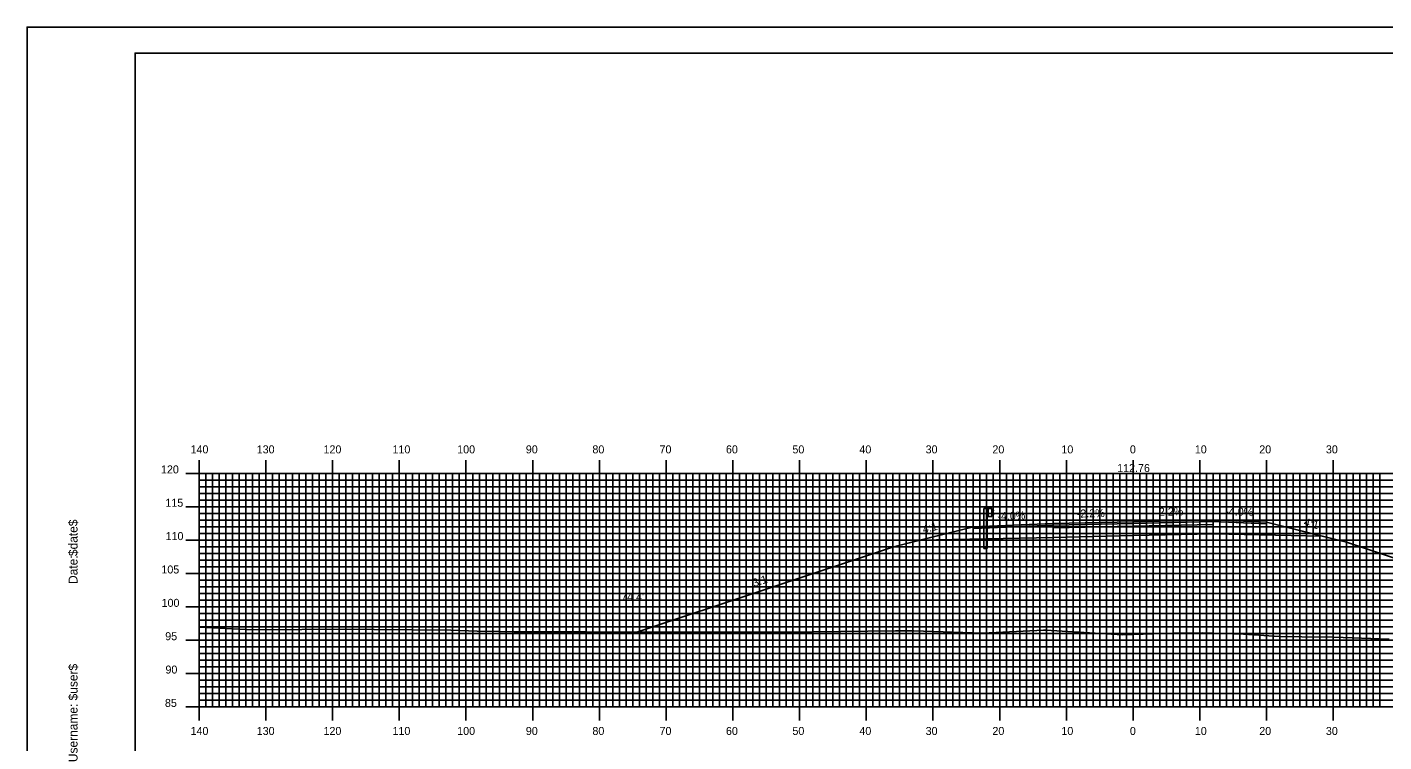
# Model space of a CAD drawing. Extents: x 1786976 to 1787319, y 442591 to 442811.
# Drawn here: x 1786975.8 to 1787179.2, y 442703.4 to 442810.5 of the extents above; entities that cross this region are included whole.
import ezdxf

# ---------------------------------------------------------------- set-up
doc = ezdxf.new("R2010")
doc.units = 0
for name, color, linetype in [('ANNOTATION', 7, 'Continuous'), ('BORDER', 7, 'Continuous'), ('D_Guardrail_Beam_Lt', 7, 'Continuous'), ('D_Roadway_Centerline', 7, 'Continuous'), ('D_Roadway_Centerline_Text', 7, 'Continuous'), ('D_Roadway_Edge_Shoulder', 7, 'Continuous'), ('D_Roadway_Edge_TW', 7, 'Continuous'), ('D_Roadway_Pavement', 7, 'Continuous'), ('D_Roadway_SlopeLines', 7, 'Continuous'), ('D_Roadway_SubGrade', 7, 'Continuous'), ('D_Text_Standard', 7, 'Continuous'), ('H_V ANNOTATION', 7, 'Continuous'), ('MAJOR', 7, 'Continuous'), ('MINOR', 7, 'Continuous'), ('PLOT BOUNDARY', 7, 'Continuous'), ('S_Roadway_Centerline', 7, 'Continuous')]:
    doc.layers.add(name, color=color, linetype=linetype)

msp = doc.modelspace()

# ---------------------------------------------------------------- linework, layer by layer
at = {"layer": 'BORDER'}
msp.add_lwpolyline([(1786991.99, 442596.67), (1787311.99, 442596.67), (1787311.99, 442806.67), (1786991.99, 442806.67)], close=True, dxfattribs=at)
at = {"layer": 'D_Guardrail_Beam_Lt'}
for p, q in [((1787119.23, 442738.39), (1787119.23, 442732.39)), ((1787119.7, 442738.39), (1787119.23, 442738.39)), ((1787120.39, 442738.39), (1787119.7, 442738.39)), ((1787119.7, 442738.39), (1787119.7, 442737.22)), ((1787119.7, 442737.22), (1787120.39, 442737.22)), ((1787119.72, 442732.39), (1787119.72, 442737.22)), ((1787119.76, 442738.39), (1787119.76, 442737.22)), ((1787119.87, 442738.39), (1787119.87, 442737.22)), ((1787120.39, 442737.22), (1787120.39, 442738.39)), ((1787120.39, 442738.3), (1787120.46, 442738.29)), ((1787120.39, 442737.84), (1787120.39, 442737.77)), ((1787120.46, 442737.32), (1787120.39, 442737.3)), ((1787120.62, 442738.04), (1787120.42, 442737.9)), ((1787120.42, 442737.7), (1787120.62, 442737.57)), ((1787120.48, 442738.28), (1787120.62, 442738.18)), ((1787120.62, 442737.42), (1787120.48, 442737.32)), ((1787119.72, 442732.39), (1787119.23, 442732.39))]:
    msp.add_line(p, q, dxfattribs=at)
for centre, major_axis, start_param, end_param in [((1787120.47, 442737.84), (-0.0789, 0), 5.323254, 6.283185), ((1787120.47, 442737.77), (-0.0789, 0), 6.283185, 7.243116), ((1787120.45, 442738.25), (0.0417, 0), 0.959931, 1.376053), ((1787120.45, 442737.36), (0.0417, 0), 4.907132, 5.323254), ((1787120.57, 442738.11), (0.0877, 0), 5.323254, 7.243116), ((1787120.57, 442737.49), (0.0877, 0), 5.323254, 7.243116)]:
    msp.add_ellipse(centre, major_axis=major_axis, ratio=0.995501, start_param=start_param, end_param=end_param, dxfattribs=at)
at = {"layer": 'D_Roadway_Centerline'}
msp.add_lwpolyline([(1787067.21, 442719.86), (1787105.66, 442732.68), (1787109.64, 442733.68), (1787117.66, 442735.68), (1787129.59, 442736.16), (1787141.59, 442736.42), (1787153.59, 442736.69), (1787161.59, 442736.37), (1787169.95, 442734.28), (1787173.59, 442733.37), (1787217.6, 442718.7)], dxfattribs=at)
at = {"layer": 'D_Roadway_Edge_Shoulder'}
for points in [[(1787153.59, 442736.69), (1787161.59, 442736.37), (1787161.59, 442736.12), (1787153.59, 442736.44)], [(1787129.59, 442736.16), (1787117.66, 442735.68), (1787117.66, 442735.43), (1787129.59, 442735.91)]]:
    msp.add_lwpolyline(points, close=True, dxfattribs=at)
at = {"layer": 'D_Roadway_Edge_TW'}
msp.add_lwpolyline([(1787129.59, 442735.91), (1787129.59, 442736.16), (1787141.59, 442736.42), (1787153.59, 442736.69), (1787153.59, 442736.44), (1787141.59, 442736.17)], close=True, dxfattribs=at)
at = {"layer": 'D_Roadway_Pavement'}
msp.add_lwpolyline([(1787129.59, 442735.49), (1787129.59, 442735.91), (1787141.59, 442736.17), (1787153.59, 442736.44), (1787153.59, 442736.02), (1787141.59, 442735.76)], close=True, dxfattribs=at)
at = {"layer": 'D_Roadway_SlopeLines'}
for points in [[(1787117.66, 442735.68), (1787105.66, 442732.68), (1787067.21, 442719.86)], [(1787161.59, 442736.37), (1787173.59, 442733.37), (1787217.6, 442718.7)]]:
    msp.add_lwpolyline(points, dxfattribs=at)
at = {"layer": 'D_Roadway_SubGrade'}
msp.add_lwpolyline([(1787129.59, 442734.08), (1787109.64, 442733.68), (1787117.66, 442735.68), (1787117.66, 442735.43), (1787129.59, 442735.91), (1787141.59, 442736.17), (1787153.59, 442736.44), (1787161.59, 442736.12), (1787161.59, 442736.37), (1787169.95, 442734.28), (1787153.59, 442734.6), (1787141.59, 442734.34)], close=True, dxfattribs=at)
at = {"layer": 'MAJOR'}
for p, q in [((1787001.59, 442745.67), (1787001.59, 442743.67)), ((1787011.59, 442745.67), (1787011.59, 442743.67)), ((1787021.59, 442745.67), (1787021.59, 442743.67)), ((1787031.59, 442745.67), (1787031.59, 442743.67)), ((1787041.59, 442745.67), (1787041.59, 442743.67)), ((1787051.59, 442745.67), (1787051.59, 442743.67)), ((1787061.59, 442745.67), (1787061.59, 442743.67)), ((1787071.59, 442745.67), (1787071.59, 442743.67)), ((1787081.59, 442745.67), (1787081.59, 442743.67)), ((1787091.59, 442745.67), (1787091.59, 442743.67)), ((1787101.59, 442745.67), (1787101.59, 442743.67)), ((1787111.59, 442745.67), (1787111.59, 442743.67)), ((1787121.59, 442745.67), (1787121.59, 442743.67)), ((1787131.59, 442745.67), (1787131.59, 442743.67)), ((1787141.59, 442745.67), (1787141.59, 442743.67)), ((1787151.59, 442745.67), (1787151.59, 442743.67)), ((1787161.59, 442745.67), (1787161.59, 442743.67)), ((1787171.59, 442745.67), (1787171.59, 442743.67)), ((1786999.59, 442743.67), (1787001.59, 442743.67)), ((1787001.59, 442743.67), (1787281.59, 442743.67)), ((1787001.59, 442708.67), (1787001.59, 442743.67)), ((1787001.59, 442708.67), (1787001.59, 442743.67)), ((1787001.59, 442743.67), (1787281.59, 442743.67)), ((1787011.59, 442708.67), (1787011.59, 442743.67)), ((1787021.59, 442708.67), (1787021.59, 442743.67)), ((1787031.59, 442708.67), (1787031.59, 442743.67)), ((1787041.59, 442708.67), (1787041.59, 442743.67)), ((1787051.59, 442708.67), (1787051.59, 442743.67)), ((1787061.59, 442708.67), (1787061.59, 442743.67)), ((1787071.59, 442708.67), (1787071.59, 442743.67)), ((1787081.59, 442708.67), (1787081.59, 442743.67)), ((1787091.59, 442708.67), (1787091.59, 442743.67)), ((1787101.59, 442708.67), (1787101.59, 442743.67)), ((1787111.59, 442708.67), (1787111.59, 442743.67)), ((1787121.59, 442708.67), (1787121.59, 442743.67)), ((1787131.59, 442708.67), (1787131.59, 442743.67)), ((1787141.59, 442708.67), (1787141.59, 442743.67)), ((1787151.59, 442708.67), (1787151.59, 442743.67)), ((1787161.59, 442708.67), (1787161.59, 442743.67)), ((1787171.59, 442708.67), (1787171.59, 442743.67)), ((1786999.59, 442738.67), (1787001.59, 442738.67)), ((1787001.59, 442738.67), (1787281.59, 442738.67)), ((1786999.59, 442733.67), (1787001.59, 442733.67)), ((1787001.59, 442733.67), (1787281.59, 442733.67)), ((1786999.59, 442728.67), (1787001.59, 442728.67)), ((1787001.59, 442728.67), (1787281.59, 442728.67)), ((1786999.59, 442723.67), (1787001.59, 442723.67)), ((1787001.59, 442723.67), (1787281.59, 442723.67)), ((1786999.59, 442718.67), (1787001.59, 442718.67)), ((1787001.59, 442718.67), (1787281.59, 442718.67)), ((1786999.59, 442713.67), (1787001.59, 442713.67)), ((1787001.59, 442713.67), (1787281.59, 442713.67)), ((1786999.59, 442708.67), (1787001.59, 442708.67)), ((1787001.59, 442708.67), (1787281.59, 442708.67)), ((1787001.59, 442708.67), (1787281.59, 442708.67)), ((1787001.59, 442706.66), (1787001.59, 442708.67)), ((1787011.59, 442706.66), (1787011.59, 442708.67)), ((1787021.59, 442706.66), (1787021.59, 442708.67)), ((1787031.59, 442706.66), (1787031.59, 442708.67)), ((1787041.59, 442706.66), (1787041.59, 442708.67)), ((1787051.59, 442706.66), (1787051.59, 442708.67)), ((1787061.59, 442706.66), (1787061.59, 442708.67)), ((1787071.59, 442706.66), (1787071.59, 442708.67)), ((1787081.59, 442706.66), (1787081.59, 442708.67)), ((1787091.59, 442706.66), (1787091.59, 442708.67)), ((1787101.59, 442706.66), (1787101.59, 442708.67)), ((1787111.59, 442706.66), (1787111.59, 442708.67)), ((1787121.59, 442706.66), (1787121.59, 442708.67)), ((1787131.59, 442706.66), (1787131.59, 442708.67)), ((1787141.59, 442706.66), (1787141.59, 442708.67)), ((1787151.59, 442706.66), (1787151.59, 442708.67)), ((1787161.59, 442706.66), (1787161.59, 442708.67)), ((1787171.59, 442706.66), (1787171.59, 442708.67))]:
    msp.add_line(p, q, dxfattribs=at)
at = {"layer": 'MINOR'}
for p, q in [((1787001.59, 442742.67), (1787281.59, 442742.67)), ((1787001.59, 442742.67), (1787003.6, 442742.67)), ((1787002.59, 442708.67), (1787002.59, 442743.67)), ((1787003.59, 442708.67), (1787003.59, 442743.67)), ((1787004.59, 442708.67), (1787004.59, 442743.67)), ((1787005.59, 442708.67), (1787005.59, 442743.67)), ((1787006.59, 442708.67), (1787006.59, 442743.67)), ((1787007.59, 442708.67), (1787007.59, 442743.67)), ((1787008.59, 442708.67), (1787008.59, 442743.67)), ((1787009.59, 442708.67), (1787009.59, 442743.67)), ((1787010.59, 442708.67), (1787010.59, 442743.67)), ((1787012.59, 442708.67), (1787012.59, 442743.67)), ((1787013.59, 442708.67), (1787013.59, 442743.67)), ((1787014.59, 442708.67), (1787014.59, 442743.67)), ((1787015.59, 442708.67), (1787015.59, 442743.67)), ((1787016.59, 442708.67), (1787016.59, 442743.67)), ((1787017.59, 442708.67), (1787017.59, 442743.67)), ((1787018.59, 442708.67), (1787018.59, 442743.67)), ((1787019.59, 442708.67), (1787019.59, 442743.67)), ((1787020.59, 442708.67), (1787020.59, 442743.67)), ((1787022.59, 442708.67), (1787022.59, 442743.67)), ((1787023.59, 442708.67), (1787023.59, 442743.67)), ((1787024.59, 442708.67), (1787024.59, 442743.67)), ((1787025.59, 442708.67), (1787025.59, 442743.67)), ((1787026.59, 442708.67), (1787026.59, 442743.67)), ((1787027.59, 442708.67), (1787027.59, 442743.67)), ((1787028.59, 442708.67), (1787028.59, 442743.67)), ((1787029.59, 442708.67), (1787029.59, 442743.67)), ((1787030.59, 442708.67), (1787030.59, 442743.67)), ((1787032.59, 442708.67), (1787032.59, 442743.67)), ((1787033.59, 442708.67), (1787033.59, 442743.67)), ((1787034.59, 442708.67), (1787034.59, 442743.67)), ((1787035.59, 442708.67), (1787035.59, 442743.67)), ((1787036.59, 442708.67), (1787036.59, 442743.67)), ((1787037.59, 442708.67), (1787037.59, 442743.67)), ((1787038.59, 442708.67), (1787038.59, 442743.67)), ((1787039.59, 442708.67), (1787039.59, 442743.67)), ((1787040.59, 442708.67), (1787040.59, 442743.67)), ((1787042.59, 442708.67), (1787042.59, 442743.67)), ((1787043.59, 442708.67), (1787043.59, 442743.67)), ((1787044.59, 442708.67), (1787044.59, 442743.67)), ((1787045.59, 442708.67), (1787045.59, 442743.67)), ((1787046.59, 442708.67), (1787046.59, 442743.67)), ((1787047.59, 442708.67), (1787047.59, 442743.67)), ((1787048.59, 442708.67), (1787048.59, 442743.67)), ((1787049.59, 442708.67), (1787049.59, 442743.67)), ((1787050.59, 442708.67), (1787050.59, 442743.67)), ((1787052.59, 442708.67), (1787052.59, 442743.67)), ((1787053.59, 442708.67), (1787053.59, 442743.67)), ((1787054.59, 442708.67), (1787054.59, 442743.67)), ((1787055.59, 442708.67), (1787055.59, 442743.67)), ((1787056.59, 442708.67), (1787056.59, 442743.67)), ((1787057.59, 442708.67), (1787057.59, 442743.67)), ((1787058.59, 442708.67), (1787058.59, 442743.67)), ((1787059.59, 442708.67), (1787059.59, 442743.67)), ((1787060.59, 442708.67), (1787060.59, 442743.67)), ((1787062.59, 442708.67), (1787062.59, 442743.67)), ((1787063.59, 442708.67), (1787063.59, 442743.67)), ((1787064.59, 442708.67), (1787064.59, 442743.67)), ((1787065.59, 442708.67), (1787065.59, 442743.67)), ((1787066.59, 442708.67), (1787066.59, 442743.67)), ((1787067.59, 442708.67), (1787067.59, 442743.67)), ((1787068.59, 442708.67), (1787068.59, 442743.67)), ((1787069.59, 442708.67), (1787069.59, 442743.67)), ((1787070.59, 442708.67), (1787070.59, 442743.67)), ((1787072.59, 442708.67), (1787072.59, 442743.67)), ((1787073.59, 442708.67), (1787073.59, 442743.67)), ((1787074.59, 442708.67), (1787074.59, 442743.67)), ((1787075.59, 442708.67), (1787075.59, 442743.67)), ((1787076.59, 442708.67), (1787076.59, 442743.67)), ((1787077.59, 442708.67), (1787077.59, 442743.67)), ((1787078.59, 442708.67), (1787078.59, 442743.67)), ((1787079.59, 442708.67), (1787079.59, 442743.67)), ((1787080.59, 442708.67), (1787080.59, 442743.67)), ((1787082.59, 442708.67), (1787082.59, 442743.67)), ((1787083.59, 442708.67), (1787083.59, 442743.67)), ((1787084.59, 442708.67), (1787084.59, 442743.67)), ((1787085.59, 442708.67), (1787085.59, 442743.67)), ((1787086.59, 442708.67), (1787086.59, 442743.67)), ((1787087.59, 442708.67), (1787087.59, 442743.67)), ((1787088.59, 442708.67), (1787088.59, 442743.67)), ((1787089.59, 442708.67), (1787089.59, 442743.67)), ((1787090.59, 442708.67), (1787090.59, 442743.67)), ((1787092.59, 442708.67), (1787092.59, 442743.67)), ((1787093.59, 442708.67), (1787093.59, 442743.67)), ((1787094.59, 442708.67), (1787094.59, 442743.67)), ((1787095.59, 442708.67), (1787095.59, 442743.67)), ((1787096.59, 442708.67), (1787096.59, 442743.67)), ((1787097.59, 442708.67), (1787097.59, 442743.67)), ((1787098.59, 442708.67), (1787098.59, 442743.67)), ((1787099.59, 442708.67), (1787099.59, 442743.67)), ((1787100.59, 442708.67), (1787100.59, 442743.67)), ((1787102.59, 442708.67), (1787102.59, 442743.67)), ((1787103.59, 442708.67), (1787103.59, 442743.67)), ((1787104.59, 442708.67), (1787104.59, 442743.67)), ((1787105.59, 442708.67), (1787105.59, 442743.67)), ((1787106.59, 442708.67), (1787106.59, 442743.67)), ((1787107.59, 442708.67), (1787107.59, 442743.67)), ((1787108.59, 442708.67), (1787108.59, 442743.67)), ((1787109.59, 442708.67), (1787109.59, 442743.67)), ((1787110.59, 442708.67), (1787110.59, 442743.67)), ((1787112.59, 442708.67), (1787112.59, 442743.67)), ((1787113.59, 442708.67), (1787113.59, 442743.67)), ((1787114.59, 442708.67), (1787114.59, 442743.67)), ((1787115.59, 442708.67), (1787115.59, 442743.67)), ((1787116.59, 442708.67), (1787116.59, 442743.67)), ((1787117.59, 442708.67), (1787117.59, 442743.67)), ((1787118.59, 442708.67), (1787118.59, 442743.67)), ((1787119.59, 442708.67), (1787119.59, 442743.67)), ((1787120.59, 442708.67), (1787120.59, 442743.67)), ((1787122.59, 442708.67), (1787122.59, 442743.67)), ((1787123.59, 442708.67), (1787123.59, 442743.67)), ((1787124.59, 442708.67), (1787124.59, 442743.67)), ((1787125.59, 442708.67), (1787125.59, 442743.67)), ((1787126.59, 442708.67), (1787126.59, 442743.67)), ((1787127.59, 442708.67), (1787127.59, 442743.67)), ((1787128.59, 442708.67), (1787128.59, 442743.67)), ((1787129.59, 442708.67), (1787129.59, 442743.67)), ((1787130.59, 442708.67), (1787130.59, 442743.67)), ((1787132.59, 442708.67), (1787132.59, 442743.67)), ((1787133.59, 442708.67), (1787133.59, 442743.67)), ((1787134.59, 442708.67), (1787134.59, 442743.67)), ((1787135.59, 442708.67), (1787135.59, 442743.67)), ((1787136.59, 442708.67), (1787136.59, 442743.67)), ((1787137.59, 442708.67), (1787137.59, 442743.67)), ((1787138.59, 442708.67), (1787138.59, 442743.67)), ((1787139.59, 442708.67), (1787139.59, 442743.67)), ((1787140.59, 442708.67), (1787140.59, 442743.67)), ((1787142.59, 442708.67), (1787142.59, 442743.67)), ((1787143.59, 442708.67), (1787143.59, 442743.67)), ((1787144.59, 442708.67), (1787144.59, 442743.67)), ((1787145.59, 442708.67), (1787145.59, 442743.67)), ((1787146.59, 442708.67), (1787146.59, 442743.67)), ((1787147.59, 442708.67), (1787147.59, 442743.67)), ((1787148.59, 442708.67), (1787148.59, 442743.67)), ((1787149.59, 442708.67), (1787149.59, 442743.67)), ((1787150.59, 442708.67), (1787150.59, 442743.67)), ((1787152.59, 442708.67), (1787152.59, 442743.67)), ((1787153.59, 442708.67), (1787153.59, 442743.67)), ((1787154.59, 442708.67), (1787154.59, 442743.67)), ((1787155.59, 442708.67), (1787155.59, 442743.67)), ((1787156.59, 442708.67), (1787156.59, 442743.67)), ((1787157.59, 442708.67), (1787157.59, 442743.67)), ((1787158.59, 442708.67), (1787158.59, 442743.67)), ((1787159.59, 442708.67), (1787159.59, 442743.67)), ((1787160.59, 442708.67), (1787160.59, 442743.67)), ((1787162.59, 442708.67), (1787162.59, 442743.67)), ((1787163.59, 442708.67), (1787163.59, 442743.67)), ((1787164.59, 442708.67), (1787164.59, 442743.67)), ((1787165.59, 442708.67), (1787165.59, 442743.67)), ((1787166.59, 442708.67), (1787166.59, 442743.67)), ((1787167.59, 442708.67), (1787167.59, 442743.67)), ((1787168.59, 442708.67), (1787168.59, 442743.67)), ((1787169.59, 442708.67), (1787169.59, 442743.67)), ((1787170.59, 442708.67), (1787170.59, 442743.67)), ((1787172.59, 442708.67), (1787172.59, 442743.67)), ((1787173.59, 442708.67), (1787173.59, 442743.67)), ((1787174.59, 442708.67), (1787174.59, 442743.67)), ((1787175.59, 442708.67), (1787175.59, 442743.67)), ((1787176.59, 442708.67), (1787176.59, 442743.67)), ((1787177.59, 442708.67), (1787177.59, 442743.67)), ((1787178.59, 442708.67), (1787178.59, 442743.67)), ((1787001.59, 442741.67), (1787281.59, 442741.67)), ((1787001.59, 442741.67), (1787003.6, 442741.67)), ((1787001.59, 442740.67), (1787281.59, 442740.67)), ((1787001.59, 442740.67), (1787003.6, 442740.67)), ((1787001.59, 442739.67), (1787281.59, 442739.67)), ((1787001.59, 442739.67), (1787003.6, 442739.67)), ((1787001.59, 442737.67), (1787281.59, 442737.67)), ((1787001.59, 442737.67), (1787003.6, 442737.67)), ((1787001.59, 442736.67), (1787281.59, 442736.67)), ((1787001.59, 442736.67), (1787003.6, 442736.67)), ((1787001.59, 442735.67), (1787281.59, 442735.67)), ((1787001.59, 442735.67), (1787003.6, 442735.67)), ((1787001.59, 442734.67), (1787281.59, 442734.67)), ((1787001.59, 442734.67), (1787003.6, 442734.67)), ((1787001.59, 442732.67), (1787281.59, 442732.67)), ((1787001.59, 442732.67), (1787003.6, 442732.67)), ((1787001.59, 442731.67), (1787281.59, 442731.67)), ((1787001.59, 442731.67), (1787003.6, 442731.67)), ((1787001.59, 442730.67), (1787281.59, 442730.67)), ((1787001.59, 442730.67), (1787003.6, 442730.67)), ((1787001.59, 442729.67), (1787281.59, 442729.67)), ((1787001.59, 442729.67), (1787003.6, 442729.67)), ((1787001.59, 442727.67), (1787281.59, 442727.67)), ((1787001.59, 442727.67), (1787003.6, 442727.67)), ((1787001.59, 442726.67), (1787281.59, 442726.67)), ((1787001.59, 442726.67), (1787003.6, 442726.67)), ((1787001.59, 442725.67), (1787281.59, 442725.67)), ((1787001.59, 442725.67), (1787003.6, 442725.67)), ((1787001.59, 442724.67), (1787281.59, 442724.67)), ((1787001.59, 442724.67), (1787003.6, 442724.67)), ((1787001.59, 442722.67), (1787281.59, 442722.67)), ((1787001.59, 442722.67), (1787003.6, 442722.67)), ((1787001.59, 442721.67), (1787281.59, 442721.67)), ((1787001.59, 442721.67), (1787003.6, 442721.67)), ((1787001.59, 442720.67), (1787281.59, 442720.67)), ((1787001.59, 442720.67), (1787003.6, 442720.67)), ((1787001.59, 442719.67), (1787281.59, 442719.67)), ((1787001.59, 442719.67), (1787003.6, 442719.67)), ((1787001.59, 442717.67), (1787281.59, 442717.67)), ((1787001.59, 442717.67), (1787003.6, 442717.67)), ((1787001.59, 442716.67), (1787281.59, 442716.67)), ((1787001.59, 442716.67), (1787003.6, 442716.67)), ((1787001.59, 442715.67), (1787281.59, 442715.67)), ((1787001.59, 442715.67), (1787003.6, 442715.67)), ((1787001.59, 442714.67), (1787281.59, 442714.67)), ((1787001.59, 442714.67), (1787003.6, 442714.67)), ((1787001.59, 442712.67), (1787281.59, 442712.67)), ((1787001.59, 442712.67), (1787003.6, 442712.67)), ((1787001.59, 442711.67), (1787281.59, 442711.67)), ((1787001.59, 442711.67), (1787003.6, 442711.67)), ((1787001.59, 442710.67), (1787281.59, 442710.67)), ((1787001.59, 442710.67), (1787003.6, 442710.67)), ((1787001.59, 442709.67), (1787281.59, 442709.67)), ((1787001.59, 442709.67), (1787003.6, 442709.67))]:
    msp.add_line(p, q, dxfattribs=at)
at = {"layer": 'PLOT BOUNDARY'}
msp.add_lwpolyline([(1786975.8, 442590.55), (1787315.8, 442590.55), (1787315.8, 442810.55), (1786975.8, 442810.55)], close=True, dxfattribs=at)
at = {"layer": 'S_Roadway_Centerline'}
msp.add_lwpolyline([(1787001.59, 442720.64), (1787008.68, 442720.3), (1787012.48, 442720.23), (1787021.49, 442720.31), (1787027.83, 442720.29), (1787039.34, 442720.16), (1787043.24, 442720.02), (1787046.71, 442719.97), (1787048.8, 442719.95), (1787059.61, 442719.93), (1787061.95, 442719.89), (1787062.58, 442719.87), (1787083.61, 442719.86), (1787089.65, 442719.88), (1787101.8, 442720.04), (1787105.97, 442720.08), (1787108.73, 442720.08), (1787119, 442719.74), (1787128.18, 442720.17), (1787128.39, 442720.17), (1787128.5, 442720.17), (1787140.02, 442719.5), (1787147.75, 442719.75), (1787152.06, 442719.78), (1787158.16, 442719.58), (1787163.48, 442719.22), (1787166.9, 442719.17), (1787171.7, 442719.13), (1787179.96, 442718.85)], dxfattribs=at)

# ---------------------------------------------------------------- texts
at = {"layer": 'ANNOTATION'}
for s, rotation, p in [('2.2%', 1.2603, (1787145.47, 442737.31)), ('-4.0%', 357.7094, (1787155.38, 442737.42)), ('-4.0%', 2.2906, (1787121.26, 442736.63)), ('-2.2%', 1.2603, (1787133.15, 442737.04)), ('4:1', 345.9638, (1787167.1, 442735.85)), ('4:1', 14.0362, (1787110.19, 442734.68)), ('3:1', 18.4348, (1787084.77, 442726.63))]:
    msp.add_text(s, height=1.2, rotation=rotation, dxfattribs=at).set_placement(p)
at = {"layer": 'BORDER'}
for s, p in [('$date$', (1786983.36, 442731.28)), ('Date:', (1786983.36, 442727.1)), ('$user$', (1786983.36, 442709.65)), ('Username:', (1786983.36, 442700.4))]:
    msp.add_text(s, height=1.339, rotation=90, dxfattribs=at).set_placement(p)
at = {"layer": 'D_Roadway_Centerline'}
for s in ['C', 'L']:
    msp.add_text(s, height=0.0146, dxfattribs=at).set_placement((1787141.59, 442736.42))
at = {"layer": 'D_Roadway_Centerline_Text'}
msp.add_text('112.76', height=1.2, dxfattribs=at).set_placement((1787139.2, 442743.87))
at = {"layer": 'D_Text_Standard'}
msp.add_text("74.4'", height=1.2, dxfattribs=at).set_placement((1787064.85, 442724.57))
at = {"layer": 'H_V ANNOTATION'}
for s, p in [('140', (1787000.3, 442746.67)), ('130', (1787010.22, 442746.67)), ('120', (1787020.23, 442746.67)), ('110', (1787030.57, 442746.67)), ('100', (1787040.27, 442746.67)), ('90', (1787050.56, 442746.67)), ('80', (1787060.54, 442746.67)), ('70', (1787070.6, 442746.67)), ('60', (1787080.56, 442746.67)), ('50', (1787090.52, 442746.67)), ('40', (1787100.56, 442746.67)), ('30', (1787110.49, 442746.67)), ('20', (1787120.5, 442746.67)), ('10', (1787130.84, 442746.67)), ('0', (1787141.11, 442746.67)), ('10', (1787150.84, 442746.67)), ('20', (1787160.5, 442746.67)), ('30', (1787170.49, 442746.67)), ('120', (1786995.87, 442743.67)), ('115', (1786996.53, 442738.67)), ('110', (1786996.56, 442733.67)), ('105', (1786995.93, 442728.67)), ('100', (1786995.96, 442723.67)), ('95', (1786996.5, 442718.67)), ('90', (1786996.54, 442713.67)), ('85', (1786996.46, 442708.67)), ('140', (1787000.3, 442704.47)), ('130', (1787010.22, 442704.47)), ('120', (1787020.23, 442704.47)), ('110', (1787030.57, 442704.47)), ('100', (1787040.27, 442704.47)), ('90', (1787050.56, 442704.47)), ('80', (1787060.54, 442704.47)), ('70', (1787070.6, 442704.47)), ('60', (1787080.56, 442704.47)), ('50', (1787090.52, 442704.47)), ('40', (1787100.56, 442704.47)), ('30', (1787110.49, 442704.47)), ('20', (1787120.5, 442704.47)), ('10', (1787130.84, 442704.47)), ('0', (1787141.11, 442704.47)), ('10', (1787150.84, 442704.47)), ('20', (1787160.5, 442704.47)), ('30', (1787170.49, 442704.47))]:
    msp.add_text(s, height=1.2, dxfattribs=at).set_placement(p)
at = {"layer": 'MAJOR'}
msp.add_text('-', height=0.012, dxfattribs=at).set_placement((1787001.58, 442708.67))

doc.saveas('drawing.dxf')
